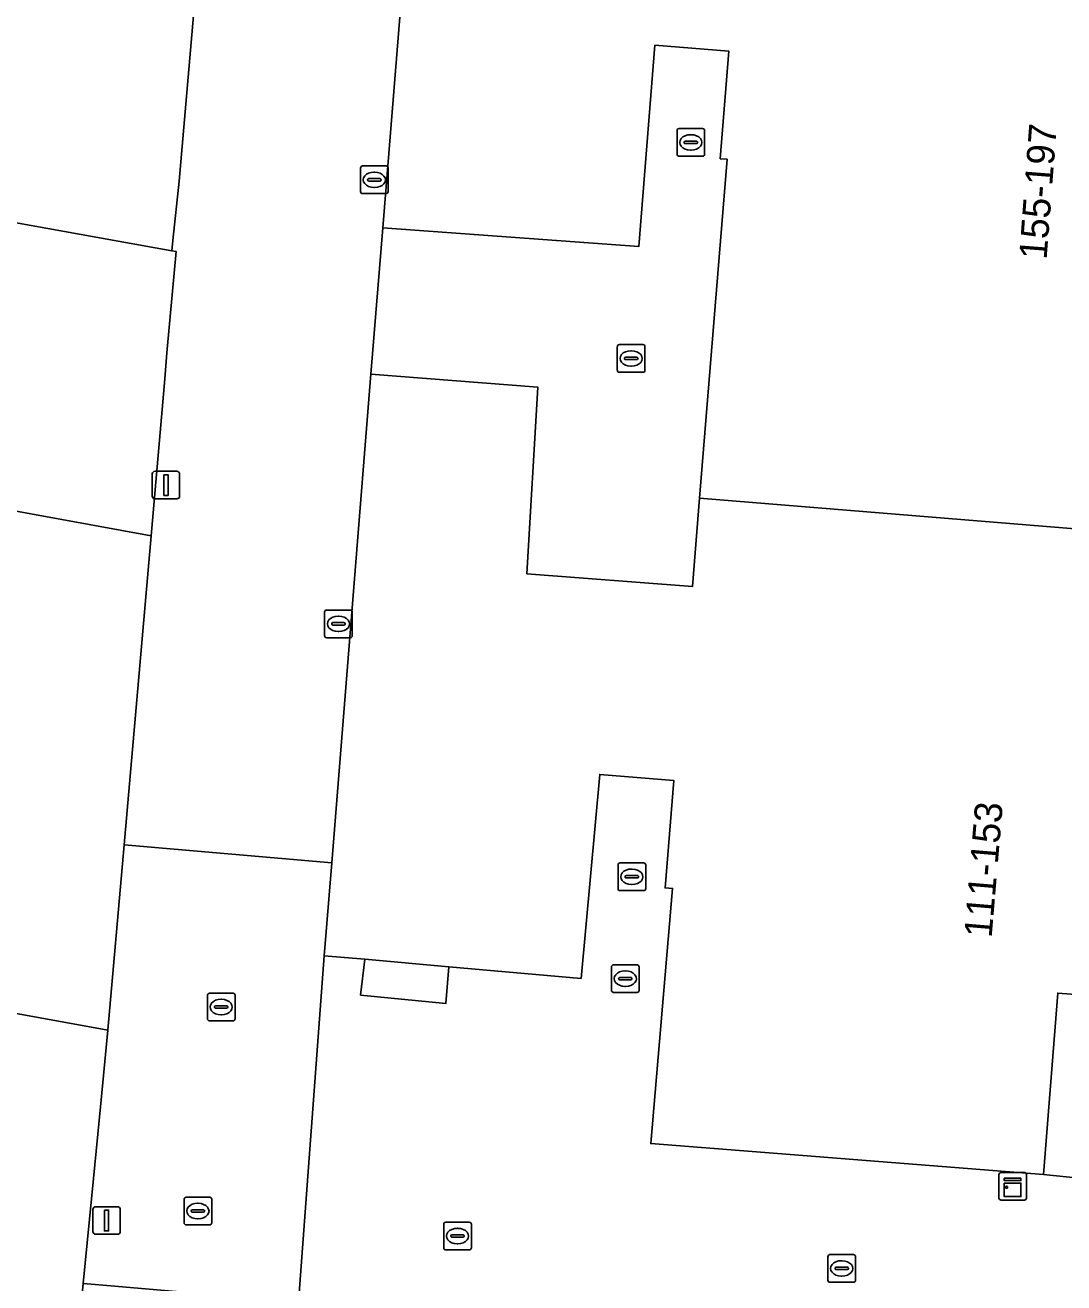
# Model space of a CAD drawing. Extents: x 160856 to 161310, y 384024 to 384878.
# Drawn here: x 161158.06 to 161195.66, y 384117.37 to 384162.87 of the extents above; entities that cross this region are included whole.
import ezdxf

# ---------------------------------------------------------------- set-up
doc = ezdxf.new("R2010")
doc.units = 0
for name, color, linetype in [('IMGEO_Erf', 7, 'Continuous'), ('IMGEO_Groenvoorziening', 7, 'Continuous'), ('IMGEO_Kast', 7, 'Continuous'), ('IMGEO_Kolk', 7, 'Continuous'), ('IMGEO_Lichtmast', 7, 'Continuous'), ('IMGEO_Pand', 7, 'Continuous'), ('IMGEO_Pand_nummerreeks', 7, 'Continuous'), ('IMGEO_Rijbaan_lokaal_open', 7, 'Continuous'), ('IMGEO_Rioolput', 7, 'Continuous'), ('IMGEO_Voetpad_open', 7, 'Continuous')]:
    doc.layers.add(name, color=color, linetype=linetype)

msp = doc.modelspace()

# ---------------------------------------------------------------- linework, layer by layer
at = {"layer": 'IMGEO_Erf'}
msp.add_lwpolyline([(161164.271, 384164.475), (161145.898, 384168.047), (161144.241, 384169.164), (161133.76, 384170.475), (161133.363, 384167.531), (161141.66, 384166.465), (161141.638, 384166.329), (161146.903, 384165.5), (161146.363, 384162.064), (161145.88, 384158.988), (161140.786, 384159.789), (161133.865, 384160.877), (161133.749, 384160.034), (161163.375, 384154.705), (161163.415, 384155.077), (161163.642, 384157.219)], close=True, dxfattribs=at)
at = {"layer": 'IMGEO_Groenvoorziening'}
msp.add_lwpolyline([(161170.36, 384129.072), (161170.205, 384127.779), (161173.292, 384127.478), (161173.394, 384128.803)], close=True, dxfattribs=at)
at = {"layer": 'IMGEO_Kast'}
for p, q in [((161193.309, 384120.436), (161193.309, 384121.277)), ((161193.309, 384121.277), (161193.309, 384120.436)), ((161193.384, 384121.361), (161194.225, 384121.361)), ((161194.225, 384121.361), (161193.384, 384121.361)), ((161194.309, 384121.286), (161194.309, 384120.445)), ((161194.309, 384120.445), (161194.309, 384121.286)), ((161194.234, 384120.361), (161193.393, 384120.361)), ((161193.393, 384120.361), (161194.234, 384120.361))]:
    msp.add_line(p, q, dxfattribs=at)
for points in [[(161193.504, 384121.151), (161194.104, 384121.151), (161194.104, 384121.066), (161193.504, 384121.066), (161193.504, 384121.151)], [(161193.504, 384120.976), (161194.104, 384120.976), (161194.104, 384120.487), (161193.504, 384120.487), (161193.504, 384120.976)]]:
    msp.add_lwpolyline(points, dxfattribs=at)
msp.add_circle((161193.588, 384120.825), 0.0377, dxfattribs=at)
for centre, start, end in [((161193.387, 384121.283), 92.4484, 184.2845), ((161193.387, 384121.283), 92.4484, 184.2845), ((161194.231, 384121.283), 2.4484, 94.2845), ((161194.231, 384121.283), 2.4484, 94.2845), ((161193.387, 384120.439), 182.4484, 274.2845), ((161193.387, 384120.439), 182.4484, 274.2845), ((161194.231, 384120.439), 272.4484, 4.2845), ((161194.231, 384120.439), 272.4484, 4.2845)]:
    msp.add_arc(centre, 0.0779, start, end, dxfattribs=at)
at = {"layer": 'IMGEO_Kolk'}
for p, q in [((161181.658, 384158.197), (161181.658, 384159.049)), ((161181.733, 384159.123), (161182.585, 384159.123)), ((161182.146, 384158.903), (161182.171, 384158.903)), ((161182.659, 384159.049), (161182.659, 384158.197)), ((161181.917, 384158.617), (161181.917, 384158.629)), ((161182.355, 384158.58), (161181.957, 384158.58)), ((161181.96, 384158.666), (161182.358, 384158.666)), ((161182.401, 384158.629), (161182.401, 384158.617)), ((161182.585, 384158.123), (161181.733, 384158.123)), ((161182.169, 384158.343), (161182.144, 384158.343)), ((161170.202, 384156.844), (161170.202, 384157.696)), ((161170.277, 384157.77), (161171.129, 384157.77)), ((161170.69, 384157.55), (161170.715, 384157.55)), ((161171.203, 384157.696), (161171.203, 384156.844)), ((161170.461, 384157.264), (161170.461, 384157.276)), ((161170.899, 384157.227), (161170.501, 384157.227)), ((161170.504, 384157.313), (161170.902, 384157.313)), ((161170.945, 384157.276), (161170.945, 384157.264)), ((161171.129, 384156.77), (161170.277, 384156.77)), ((161170.713, 384156.99), (161170.688, 384156.99)), ((161179.498, 384150.381), (161179.498, 384151.233)), ((161179.573, 384151.307), (161180.425, 384151.307)), ((161180.499, 384151.233), (161180.499, 384150.381)), ((161179.757, 384150.801), (161179.757, 384150.813)), ((161180.195, 384150.764), (161179.797, 384150.764)), ((161179.8, 384150.85), (161180.198, 384150.85)), ((161179.986, 384151.087), (161180.011, 384151.087)), ((161180.241, 384150.813), (161180.241, 384150.801)), ((161180.425, 384150.307), (161179.573, 384150.307)), ((161180.009, 384150.527), (161179.984, 384150.527)), ((161168.903, 384140.781), (161168.903, 384141.633)), ((161168.978, 384141.707), (161169.83, 384141.707)), ((161169.904, 384141.633), (161169.904, 384140.781)), ((161169.162, 384141.201), (161169.162, 384141.213)), ((161169.6, 384141.164), (161169.202, 384141.164)), ((161169.205, 384141.25), (161169.603, 384141.25)), ((161169.391, 384141.487), (161169.416, 384141.487)), ((161169.646, 384141.213), (161169.646, 384141.201)), ((161169.83, 384140.707), (161168.978, 384140.707)), ((161169.414, 384140.927), (161169.389, 384140.927)), ((161179.523, 384131.631), (161179.523, 384132.483)), ((161179.598, 384132.557), (161180.45, 384132.557)), ((161180.524, 384132.483), (161180.524, 384131.631)), ((161179.782, 384132.051), (161179.782, 384132.063)), ((161180.22, 384132.014), (161179.822, 384132.014)), ((161179.825, 384132.1), (161180.223, 384132.1)), ((161180.011, 384132.337), (161180.036, 384132.337)), ((161180.266, 384132.063), (161180.266, 384132.051)), ((161180.45, 384131.557), (161179.598, 384131.557)), ((161180.034, 384131.777), (161180.009, 384131.777)), ((161179.286, 384127.946), (161179.286, 384128.798)), ((161179.361, 384128.872), (161180.213, 384128.872)), ((161180.287, 384128.798), (161180.287, 384127.946)), ((161179.545, 384128.366), (161179.545, 384128.378)), ((161179.588, 384128.415), (161179.986, 384128.415)), ((161179.774, 384128.652), (161179.799, 384128.652)), ((161180.029, 384128.378), (161180.029, 384128.366)), ((161179.983, 384128.329), (161179.585, 384128.329)), ((161179.797, 384128.092), (161179.772, 384128.092)), ((161164.661, 384126.919), (161164.661, 384127.771)), ((161164.736, 384127.845), (161165.588, 384127.845)), ((161165.149, 384127.625), (161165.174, 384127.625)), ((161165.662, 384127.771), (161165.662, 384126.919)), ((161180.213, 384127.872), (161179.361, 384127.872)), ((161164.92, 384127.339), (161164.92, 384127.351)), ((161165.358, 384127.302), (161164.96, 384127.302)), ((161164.963, 384127.388), (161165.361, 384127.388)), ((161165.172, 384127.065), (161165.147, 384127.065)), ((161165.404, 384127.351), (161165.404, 384127.339)), ((161165.588, 384126.845), (161164.736, 384126.845)), ((161173.213, 384118.634), (161173.213, 384119.486)), ((161173.288, 384119.56), (161174.14, 384119.56)), ((161173.701, 384119.34), (161173.726, 384119.34)), ((161174.214, 384119.486), (161174.214, 384118.634)), ((161173.472, 384119.054), (161173.472, 384119.066)), ((161173.91, 384119.017), (161173.512, 384119.017)), ((161173.515, 384119.103), (161173.913, 384119.103)), ((161173.956, 384119.066), (161173.956, 384119.054)), ((161174.14, 384118.56), (161173.288, 384118.56)), ((161173.724, 384118.78), (161173.699, 384118.78)), ((161187.193, 384118.388), (161188.045, 384118.388)), ((161187.118, 384117.462), (161187.118, 384118.314)), ((161187.377, 384117.882), (161187.377, 384117.894)), ((161187.42, 384117.931), (161187.818, 384117.931)), ((161187.606, 384118.168), (161187.631, 384118.168)), ((161187.861, 384117.894), (161187.861, 384117.882)), ((161188.119, 384118.314), (161188.119, 384117.462)), ((161187.815, 384117.845), (161187.417, 384117.845)), ((161187.629, 384117.608), (161187.604, 384117.608)), ((161188.045, 384117.388), (161187.193, 384117.388))]:
    msp.add_line(p, q, dxfattribs=at)
for points in [[(161181.658, 384158.197), (161181.658, 384159.049)], [(161181.733, 384159.123), (161182.585, 384159.123)], [(161182.659, 384159.049), (161182.659, 384158.197)], [(161182.585, 384158.123), (161181.733, 384158.123)], [(161170.202, 384156.844), (161170.202, 384157.696)], [(161170.277, 384157.77), (161171.129, 384157.77)], [(161171.203, 384157.696), (161171.203, 384156.844)], [(161171.129, 384156.77), (161170.277, 384156.77)], [(161179.498, 384150.381), (161179.498, 384151.233)], [(161179.573, 384151.307), (161180.425, 384151.307)], [(161180.499, 384151.233), (161180.499, 384150.381)], [(161180.425, 384150.307), (161179.573, 384150.307)], [(161168.903, 384140.781), (161168.903, 384141.633)], [(161168.978, 384141.707), (161169.83, 384141.707)], [(161169.904, 384141.633), (161169.904, 384140.781)], [(161169.83, 384140.707), (161168.978, 384140.707)], [(161179.523, 384131.631), (161179.523, 384132.483)], [(161179.598, 384132.557), (161180.45, 384132.557)], [(161180.524, 384132.483), (161180.524, 384131.631)], [(161180.45, 384131.557), (161179.598, 384131.557)], [(161179.286, 384127.946), (161179.286, 384128.798)], [(161179.361, 384128.872), (161180.213, 384128.872)], [(161180.287, 384128.798), (161180.287, 384127.946)], [(161164.661, 384126.919), (161164.661, 384127.771)], [(161164.736, 384127.845), (161165.588, 384127.845)], [(161165.662, 384127.771), (161165.662, 384126.919)], [(161180.213, 384127.872), (161179.361, 384127.872)], [(161165.588, 384126.845), (161164.736, 384126.845)], [(161173.213, 384118.634), (161173.213, 384119.486)], [(161173.288, 384119.56), (161174.14, 384119.56)], [(161174.214, 384119.486), (161174.214, 384118.634)], [(161174.14, 384118.56), (161173.288, 384118.56)], [(161187.193, 384118.388), (161188.045, 384118.388)], [(161187.118, 384117.462), (161187.118, 384118.314)], [(161188.119, 384118.314), (161188.119, 384117.462)], [(161188.045, 384117.388), (161187.193, 384117.388)]]:
    msp.add_lwpolyline(points, dxfattribs=at)
for centre, radius, start, end in [((161181.735, 384159.047), 0.0765, 91.552, 178.448), ((161181.735, 384159.047), 0.0765, 91.552, 178.448), ((161182.583, 384159.047), 0.0765, 1.552, 88.448), ((161182.583, 384159.047), 0.0765, 1.552, 88.448), ((161181.957, 384158.626), 0.0403, 85.8775, 175.7526), ((161181.954, 384158.616), 0.0366, 178.938, 274.7102), ((161182.358, 384158.623), 0.043, 264.8664, 352.4533), ((161182.362, 384158.628), 0.0386, 1.7309, 96.639), ((161181.735, 384158.199), 0.0765, 181.552, 268.448), ((161181.735, 384158.199), 0.0765, 181.552, 268.448), ((161182.583, 384158.199), 0.0765, 271.552, 358.448), ((161182.583, 384158.199), 0.0765, 271.552, 358.448), ((161170.279, 384157.694), 0.0765, 91.552, 178.448), ((161170.279, 384157.694), 0.0765, 91.552, 178.448), ((161171.127, 384157.694), 0.0765, 1.552, 88.448), ((161171.127, 384157.694), 0.0765, 1.552, 88.448), ((161170.501, 384157.273), 0.0403, 85.8775, 175.7526), ((161170.498, 384157.263), 0.0366, 178.938, 274.7102), ((161170.902, 384157.27), 0.043, 264.8664, 352.4533), ((161170.906, 384157.275), 0.0386, 1.7309, 96.639), ((161170.279, 384156.846), 0.0765, 181.552, 268.448), ((161170.279, 384156.846), 0.0765, 181.552, 268.448), ((161171.127, 384156.846), 0.0765, 271.552, 358.448), ((161171.127, 384156.846), 0.0765, 271.552, 358.448), ((161179.575, 384151.231), 0.0765, 91.552, 178.448), ((161179.575, 384151.231), 0.0765, 91.552, 178.448), ((161180.423, 384151.231), 0.0765, 1.552, 88.448), ((161180.423, 384151.231), 0.0765, 1.552, 88.448), ((161179.797, 384150.81), 0.0403, 85.8775, 175.7526), ((161179.794, 384150.8), 0.0366, 178.938, 274.7102), ((161180.198, 384150.807), 0.043, 264.8664, 352.4533), ((161180.202, 384150.812), 0.0386, 1.7309, 96.639), ((161179.575, 384150.383), 0.0765, 181.552, 268.448), ((161179.575, 384150.383), 0.0765, 181.552, 268.448), ((161180.423, 384150.383), 0.0765, 271.552, 358.448), ((161180.423, 384150.383), 0.0765, 271.552, 358.448), ((161168.98, 384141.631), 0.0765, 91.552, 178.448), ((161168.98, 384141.631), 0.0765, 91.552, 178.448), ((161169.828, 384141.631), 0.0765, 1.552, 88.448), ((161169.828, 384141.631), 0.0765, 1.552, 88.448), ((161169.202, 384141.21), 0.0403, 85.8775, 175.7526), ((161169.199, 384141.2), 0.0366, 178.938, 274.7102), ((161169.603, 384141.207), 0.043, 264.8664, 352.4533), ((161169.607, 384141.212), 0.0386, 1.7309, 96.639), ((161168.98, 384140.783), 0.0765, 181.552, 268.448), ((161168.98, 384140.783), 0.0765, 181.552, 268.448), ((161169.828, 384140.783), 0.0765, 271.552, 358.448), ((161169.828, 384140.783), 0.0765, 271.552, 358.448), ((161179.6, 384132.481), 0.0765, 91.552, 178.448), ((161179.6, 384132.481), 0.0765, 91.552, 178.448), ((161180.448, 384132.481), 0.0765, 1.552, 88.448), ((161180.448, 384132.481), 0.0765, 1.552, 88.448), ((161179.822, 384132.06), 0.0403, 85.8775, 175.7526), ((161179.819, 384132.05), 0.0366, 178.938, 274.7102), ((161180.223, 384132.057), 0.043, 264.8664, 352.4533), ((161180.227, 384132.062), 0.0386, 1.7309, 96.639), ((161179.6, 384131.633), 0.0765, 181.552, 268.448), ((161179.6, 384131.633), 0.0765, 181.552, 268.448), ((161180.448, 384131.633), 0.0765, 271.552, 358.448), ((161180.448, 384131.633), 0.0765, 271.552, 358.448), ((161179.363, 384128.796), 0.0765, 91.552, 178.448), ((161179.363, 384128.796), 0.0765, 91.552, 178.448), ((161180.211, 384128.796), 0.0765, 1.552, 88.448), ((161180.211, 384128.796), 0.0765, 1.552, 88.448), ((161179.585, 384128.375), 0.0403, 85.8775, 175.7526), ((161179.582, 384128.365), 0.0366, 178.938, 274.7102), ((161179.986, 384128.372), 0.043, 264.8664, 352.4533), ((161179.99, 384128.377), 0.0386, 1.7309, 96.639), ((161179.363, 384127.948), 0.0765, 181.552, 268.448), ((161179.363, 384127.948), 0.0765, 181.552, 268.448), ((161180.211, 384127.948), 0.0765, 271.552, 358.448), ((161180.211, 384127.948), 0.0765, 271.552, 358.448), ((161164.738, 384127.769), 0.0765, 91.552, 178.448), ((161164.738, 384127.769), 0.0765, 91.552, 178.448), ((161165.586, 384127.769), 0.0765, 1.552, 88.448), ((161165.586, 384127.769), 0.0765, 1.552, 88.448), ((161164.96, 384127.348), 0.0403, 85.8775, 175.7526), ((161164.957, 384127.338), 0.0366, 178.938, 274.7102), ((161165.361, 384127.345), 0.043, 264.8664, 352.4533), ((161165.365, 384127.35), 0.0386, 1.7309, 96.639), ((161164.738, 384126.921), 0.0765, 181.552, 268.448), ((161164.738, 384126.921), 0.0765, 181.552, 268.448), ((161165.586, 384126.921), 0.0765, 271.552, 358.448), ((161165.586, 384126.921), 0.0765, 271.552, 358.448), ((161173.29, 384119.484), 0.0765, 91.552, 178.448), ((161173.29, 384119.484), 0.0765, 91.552, 178.448), ((161174.138, 384119.484), 0.0765, 1.552, 88.448), ((161174.138, 384119.484), 0.0765, 1.552, 88.448), ((161173.512, 384119.063), 0.0403, 85.8775, 175.7526), ((161173.509, 384119.053), 0.0366, 178.938, 274.7102), ((161173.913, 384119.06), 0.043, 264.8664, 352.4533), ((161173.917, 384119.065), 0.0386, 1.7309, 96.639), ((161173.29, 384118.636), 0.0765, 181.552, 268.448), ((161173.29, 384118.636), 0.0765, 181.552, 268.448), ((161174.138, 384118.636), 0.0765, 271.552, 358.448), ((161174.138, 384118.636), 0.0765, 271.552, 358.448), ((161187.195, 384118.312), 0.0765, 91.552, 178.448), ((161187.195, 384118.312), 0.0765, 91.552, 178.448), ((161188.043, 384118.312), 0.0765, 1.552, 88.448), ((161188.043, 384118.312), 0.0765, 1.552, 88.448), ((161187.417, 384117.891), 0.0403, 85.8775, 175.7526), ((161187.414, 384117.881), 0.0366, 178.938, 274.7102), ((161187.818, 384117.888), 0.043, 264.8664, 352.4533), ((161187.822, 384117.893), 0.0386, 1.7309, 96.639), ((161187.195, 384117.464), 0.0765, 181.552, 268.448), ((161187.195, 384117.464), 0.0765, 181.552, 268.448), ((161188.043, 384117.464), 0.0765, 271.552, 358.448), ((161188.043, 384117.464), 0.0765, 271.552, 358.448)]:
    msp.add_arc(centre, radius, start, end, dxfattribs=at)
for centre, major_axis, ratio, start_param, end_param in [((161182.145, 384158.623), (-0.387, 0.002), 0.722429, 4.712389, 7.853982), ((161182.17, 384158.623), (-0.39, 0.002), 0.717154, 1.570796, 4.712389), ((161170.689, 384157.27), (-0.387, 0.002), 0.722429, 4.712389, 7.853982), ((161170.714, 384157.27), (-0.39, 0.002), 0.717154, 1.570796, 4.712389), ((161179.985, 384150.807), (-0.387, 0.002), 0.722429, 4.712389, 7.853982), ((161180.01, 384150.807), (-0.39, 0.002), 0.717154, 1.570796, 4.712389), ((161169.39, 384141.207), (-0.387, 0.002), 0.722429, 4.712389, 7.853982), ((161169.415, 384141.207), (-0.39, 0.002), 0.717154, 1.570796, 4.712389), ((161180.01, 384132.057), (-0.387, 0.002), 0.722429, 4.712389, 7.853982), ((161180.035, 384132.057), (-0.39, 0.002), 0.717154, 1.570796, 4.712389), ((161179.773, 384128.372), (-0.387, 0.002), 0.722429, 4.712389, 7.853982), ((161179.798, 384128.372), (-0.39, 0.002), 0.717154, 1.570796, 4.712389), ((161165.148, 384127.345), (-0.387, 0.002), 0.722429, 4.712389, 7.853982), ((161165.173, 384127.345), (-0.39, 0.002), 0.717154, 1.570796, 4.712389), ((161173.7, 384119.06), (-0.387, 0.002), 0.722429, 4.712389, 7.853982), ((161173.725, 384119.06), (-0.39, 0.002), 0.717154, 1.570796, 4.712389), ((161187.605, 384117.888), (-0.387, 0.002), 0.722429, 4.712389, 7.853982), ((161187.63, 384117.888), (-0.39, 0.002), 0.717154, 1.570796, 4.712389)]:
    msp.add_ellipse(centre, major_axis=major_axis, ratio=ratio, start_param=start_param, end_param=end_param, dxfattribs=at)
at = {"layer": 'IMGEO_Lichtmast'}
for p, q in [((161162.665, 384145.828), (161162.665, 384146.628)), ((161162.665, 384146.628), (161162.665, 384145.828)), ((161162.765, 384146.728), (161163.555, 384146.728)), ((161163.555, 384146.728), (161162.765, 384146.728)), ((161163.655, 384146.628), (161163.655, 384145.828)), ((161163.655, 384145.828), (161163.655, 384146.628)), ((161163.555, 384145.728), (161162.765, 384145.728)), ((161162.765, 384145.728), (161163.555, 384145.728)), ((161160.516, 384119.223), (161160.516, 384120.023)), ((161160.516, 384120.023), (161160.516, 384119.223)), ((161160.616, 384120.123), (161161.406, 384120.123)), ((161161.406, 384120.123), (161160.616, 384120.123)), ((161161.506, 384120.023), (161161.506, 384119.223)), ((161161.506, 384119.223), (161161.506, 384120.023)), ((161161.406, 384119.123), (161160.616, 384119.123)), ((161160.616, 384119.123), (161161.406, 384119.123))]:
    msp.add_line(p, q, dxfattribs=at)
for points in [[(161163.085, 384146.603), (161163.235, 384146.603), (161163.235, 384145.853), (161163.085, 384145.853), (161163.085, 384146.603)], [(161160.936, 384119.998), (161161.086, 384119.998), (161161.086, 384119.248), (161160.936, 384119.248), (161160.936, 384119.998)]]:
    msp.add_lwpolyline(points, dxfattribs=at)
for centre, start, end in [((161162.765, 384146.628), 90, 180), ((161162.765, 384146.628), 90, 180), ((161163.555, 384146.628), 0, 90), ((161163.555, 384146.628), 360, 90), ((161162.765, 384145.828), 180, 270), ((161162.765, 384145.828), 180, 270), ((161163.555, 384145.828), 270, 0), ((161163.555, 384145.828), 270, 0), ((161160.616, 384120.023), 90, 180), ((161160.616, 384120.023), 90, 180), ((161161.406, 384120.023), 0, 90), ((161161.406, 384120.023), 360, 90), ((161160.616, 384119.223), 180, 270), ((161160.616, 384119.223), 180, 270), ((161161.406, 384119.223), 270, 0), ((161161.406, 384119.223), 270, 0)]:
    msp.add_arc(centre, 0.1, start, end, dxfattribs=at)
at = {"layer": 'IMGEO_Pand'}
for points in [[(161184.731, 384172.149), (161184.469, 384168.976), (161178.209, 384169.461), (161178.682, 384176.195), (161172.701, 384176.643), (161171.684, 384163.91), (161171.015, 384155.539), (161180.272, 384154.856), (161180.859, 384162.136), (161183.537, 384161.918), (161183.221, 384158.032), (161183.471, 384158.012), (161182.477, 384145.749), (161196.8, 384144.59), (161197.563, 384154.307), (161198.825, 384154.208), (161199.379, 384161.266), (161198.163, 384161.362), (161198.917, 384170.976)], [(161163.197, 384151.012), (161163.398, 384153.237), (161163.528, 384154.677), (161163.375, 384154.705), (161133.749, 384160.034), (161132.323, 384152.557), (161141.361, 384150.833), (161141.586, 384152.012), (161143.943, 384151.562), (161145.582, 384152.676), (161145.72, 384153.403), (161155.447, 384151.548), (161154.367, 384145.888), (161157.102, 384145.393), (161157.131, 384145.388), (161162.62, 384144.394), (161163.115, 384150.069)], [(161196.8, 384144.59), (161182.477, 384145.749), (161182.219, 384142.562), (161176.225, 384143.022), (161176.622, 384149.768), (161170.578, 384150.241), (161169.161, 384132.561), (161168.892, 384129.202), (161170.36, 384129.072), (161173.394, 384128.803), (161178.188, 384128.378), (161178.864, 384135.76), (161181.541, 384135.542), (161181.225, 384131.656), (161181.495, 384131.634), (161180.71, 384122.407), (161194.922, 384121.291), (161195.437, 384127.847), (161196.728, 384127.745), (161197.28, 384134.771), (161196.037, 384134.869)], [(161161.061, 384126.511), (161161.646, 384133.216), (161162.62, 384144.394), (161157.131, 384145.388), (161153.888, 384127.815)], [(161161.061, 384126.511), (161153.888, 384127.815), (161152.126, 384118.118), (161152.021, 384117.543), (161154.949, 384117.011), (161155.125, 384116.979), (161160.044, 384116.084), (161160.167, 384117.348), (161160.537, 384121.14), (161160.79, 384123.737)]]:
    msp.add_lwpolyline(points, close=True, dxfattribs=at)
at = {"layer": 'IMGEO_Rijbaan_lokaal_open'}
for points in [[(161163.642, 384157.219), (161163.415, 384155.077), (161163.375, 384154.705), (161163.528, 384154.677), (161163.398, 384153.237), (161163.197, 384151.012), (161163.115, 384150.069), (161162.62, 384144.394), (161161.646, 384133.216), (161169.161, 384132.561), (161170.578, 384150.241), (161171.015, 384155.539), (161171.684, 384163.91), (161164.271, 384164.475)], [(161170.578, 384150.241), (161176.622, 384149.768), (161176.225, 384143.022), (161182.219, 384142.562), (161182.477, 384145.749), (161183.471, 384158.012), (161183.221, 384158.032), (161183.537, 384161.918), (161180.859, 384162.136), (161180.272, 384154.856), (161171.015, 384155.539)], [(161175.223, 384114.926), (161194.793, 384113.414), (161196.883, 384113.324), (161197.483, 384121.051), (161196.213, 384121.151), (161194.922, 384121.291), (161180.71, 384122.407), (161181.495, 384131.634), (161181.225, 384131.656), (161181.541, 384135.542), (161178.864, 384135.76), (161178.188, 384128.378), (161173.394, 384128.803), (161173.292, 384127.478), (161170.205, 384127.779), (161170.36, 384129.072), (161168.892, 384129.202), (161167.964, 384116.669), (161173.824, 384116.159), (161173.719, 384115.041)], [(161161.061, 384126.511), (161160.79, 384123.737), (161160.537, 384121.14), (161160.167, 384117.348), (161161.314, 384117.248), (161167.964, 384116.669), (161168.892, 384129.202), (161169.161, 384132.561), (161161.646, 384133.216)]]:
    msp.add_lwpolyline(points, close=True, dxfattribs=at)
at = {"layer": 'IMGEO_Rioolput'}
for p, q in [((161163.817, 384119.54), (161163.817, 384120.392)), ((161163.892, 384120.466), (161164.744, 384120.466)), ((161164.305, 384120.246), (161164.33, 384120.246)), ((161164.818, 384120.392), (161164.818, 384119.54)), ((161164.076, 384119.96), (161164.076, 384119.972)), ((161164.514, 384119.923), (161164.116, 384119.923)), ((161164.119, 384120.009), (161164.517, 384120.009)), ((161164.56, 384119.972), (161164.56, 384119.96)), ((161164.744, 384119.466), (161163.892, 384119.466)), ((161164.328, 384119.686), (161164.303, 384119.686))]:
    msp.add_line(p, q, dxfattribs=at)
for points in [[(161163.817, 384119.54), (161163.817, 384120.392)], [(161163.892, 384120.466), (161164.744, 384120.466)], [(161164.818, 384120.392), (161164.818, 384119.54)], [(161164.744, 384119.466), (161163.892, 384119.466)]]:
    msp.add_lwpolyline(points, dxfattribs=at)
for centre, radius, start, end in [((161163.894, 384120.39), 0.0765, 91.552, 178.448), ((161163.894, 384120.39), 0.0765, 91.552, 178.448), ((161164.742, 384120.39), 0.0765, 1.552, 88.448), ((161164.742, 384120.39), 0.0765, 1.552, 88.448), ((161164.116, 384119.969), 0.0403, 85.8775, 175.7526), ((161164.113, 384119.959), 0.0366, 178.938, 274.7102), ((161164.517, 384119.966), 0.043, 264.8664, 352.4533), ((161164.521, 384119.971), 0.0386, 1.7309, 96.639), ((161163.894, 384119.542), 0.0765, 181.552, 268.448), ((161163.894, 384119.542), 0.0765, 181.552, 268.448), ((161164.742, 384119.542), 0.0765, 271.552, 358.448), ((161164.742, 384119.542), 0.0765, 271.552, 358.448)]:
    msp.add_arc(centre, radius, start, end, dxfattribs=at)
for centre, major_axis, ratio, start_param, end_param in [((161164.304, 384119.966), (-0.387, 0.002), 0.722429, 4.712389, 7.853982), ((161164.329, 384119.966), (-0.39, 0.002), 0.717154, 1.570796, 4.712389)]:
    msp.add_ellipse(centre, major_axis=major_axis, ratio=ratio, start_param=start_param, end_param=end_param, dxfattribs=at)
at = {"layer": 'IMGEO_Voetpad_open'}
msp.add_lwpolyline([(161196.213, 384121.151), (161196.728, 384127.745), (161195.437, 384127.847), (161194.922, 384121.291)], close=True, dxfattribs=at)

# ---------------------------------------------------------------- texts
at = {"layer": 'IMGEO_Pand_nummerreeks'}
for s, rotation, p in [('155-197', 85.6199, (161195.034, 384154.366)), ('111-153', 85.2022, (161193.044, 384129.829))]:
    msp.add_text(s, height=1, rotation=rotation, dxfattribs=at).set_placement(p)

doc.saveas('drawing.dxf')
